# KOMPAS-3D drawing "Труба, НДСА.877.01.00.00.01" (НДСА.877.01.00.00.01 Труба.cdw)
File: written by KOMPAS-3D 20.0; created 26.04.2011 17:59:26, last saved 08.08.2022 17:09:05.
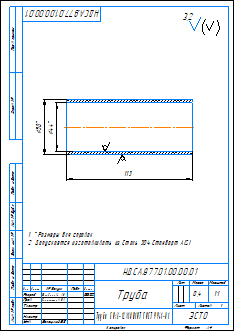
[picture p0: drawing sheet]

Sheet 1: A4, portrait

Document properties: Автор: Мочегов И.Н.; Организация: ЭСТО-Вакуум; Масса: 0.395434; Знак неуказанной шероховатости: 4; Параметр неуказанной шероховатости: 3,2; 311081399727: <item xmlns="http://appius.ru/pdm" xmlns:xs="http://www.w3.org/2001/XMLSchema" xmlns:xsi="http://www.w3.org/2001/XMLSchema-instance" xsi:type="item">  <element xmlns:d2p1="http://v8.1c.ru/8.1/data/enterprise/current-config" xsi:type="d2p1:CatalogRef.aps_Элемен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; 311081399827: <item xmlns="http://appius.ru/pdm" xmlns:xs="http://www.w3.org/2001/XMLSchema" xmlns:xsi="http://www.w3.org/2001/XMLSchema-instance" xsi:type="item">  <element xmlns:d2p1="http://v8.1c.ru/8.1/data/enterprise/current-config" xsi:type="d2p1:CatalogRef.aps_Элемен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; 255363910193: <item xmlns="http://appius.ru/pdm" xmlns:xs="http://www.w3.org/2001/XMLSchema" xmlns:xsi="http://www.w3.org/2001/XMLSchema-instance" xsi:type="item">  <element xmlns:d2p1="http://v8.1c.ru/8.1/data/enterprise/current-config" xsi:type="d2p1:CatalogRef.aps_Элемен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; 255363910293: <item xmlns="http://appius.ru/pdm" xmlns:xs="http://www.w3.org/2001/XMLSchema" xmlns:xsi="http://www.w3.org/2001/XMLSchema-instance" xsi:type="item">  <element xmlns:d2p1="http://v8.1c.ru/8.1/data/enterprise/current-config" xsi:type="d2p1:CatalogRef.aps_Элемен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; PDM_DOCXDTO: <item xmlns="http://appius.ru/pdm" xmlns:xs="http://www.w3.org/2001/XMLSchema" xmlns:xsi="http://www.w3.org/2001/XMLSchema-instance" xsi:type="item">  <element xmlns:d2p1="http://v8.1c.ru/8.1/data/enterprise/current-config" xsi:type="d2p1:CatalogRef.aps_Элемен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; PDM_ITEMXDTO: <item xmlns="http://appius.ru/pdm" xmlns:xs="http://www.w3.org/2001/XMLSchema" xmlns:xsi="http://www.w3.org/2001/XMLSchema-instance" xsi:type="item">  <element xmlns:d2p1="http://v8.1c.ru/8.1/data/enterprise/current-config" xsi:type="d2p1:CatalogRef.aps_Элемен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; PLM_CDWXDTO: <item xmlns="http://appius.ru/pdm" xmlns:xs="http://www.w3.org/2001/XMLSchema" xmlns:xsi="http://www.w3.org/2001/XMLSchema-instance" xsi:type="item">  <element xmlns:d2p1="http://v8.1c.ru/8.1/data/enterprise/current-config" xsi:type="d2p1:CatalogRef.aps_Элемен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; Полное имя файла: ..\..\PLM\НДСА.877.01.00.00.01 Труба.m3d; PDM_DOCXDTO: <item xmlns="http://appius.ru/pdm" xmlns:xs="http://www.w3.org/2001/XMLSchema" xmlns:xsi="http://www.w3.org/2001/XMLSchema-instance" xsi:type="item">  <element xmlns:d2p1="http://v8.1c.ru/8.1/data/enterprise/current-config" xsi:type="d2p1:CatalogRef.aps_Элемен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; PDM_ITEMXDTO: <item xmlns="http://appius.ru/pdm" xmlns:xs="http://www.w3.org/2001/XMLSchema" xmlns:xsi="http://www.w3.org/2001/XMLSchema-instance" xsi:type="item">  <element xmlns:d2p1="http://v8.1c.ru/8.1/data/enterprise/current-config" xsi:type="d2p1:CatalogRef.aps_Элемен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

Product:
- Part/product: Труба  | designation НДСА.877.01.00.00.01
    Материал: Труба  50х3-12Х18Н10Т ГОСТ 9941-81 (density 7900 kg/m3)
    Масса: 0.395434
    Раздел спецификации: Детали
    Форматы листов документа: A4
    additional columns: <item xmlns="http://appius.ru/pdm" xmlns:xs="http://www.w3.org/2001/XMLSchema" x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; <item xmlns="http://appius.ru/pdm" xmlns:xs="http://www.w3.org/2001/XMLSchema" x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; <item xmlns="http://appius.ru/pdm" xmlns:xs="http://www.w3.org/2001/XMLSchema" x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; <item xmlns="http://appius.ru/pdm" xmlns:xs="http://www.w3.org/2001/XMLSchema" x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; <item xmlns="http://appius.ru/pdm" xmlns:xs="http://www.w3.org/2001/XMLSchema" x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; <item xmlns="http://appius.ru/pdm" xmlns:xs="http://www.w3.org/2001/XMLSchema" x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

Title block, sheet 1: Наименование: Труба; designation: НДСА.877.01.00.00.01; Материал: Труба  50х3-12Х18Н10Т ГОСТ 9941-81; Масса: 0,4; scale: 1:1; Количество листов документа: 1; organisation: ЭСТО; Форматы листов документа: A4; stored path: C:\_Мочегов\Приказ №2-11 Разработка нагревателей\Накальный (Гор) УКРД.772.05-01\_В PDM\УКРД.772.08.02.00.01 Труба.cdw; Разработал: Щербакова А.В.; Проверил: Горностаев П.А.; Утвердил: Белецкий В.Е.; Разработал, date: 08.08.2022

Views: Вид 1, Местный разрез 1, Спереди
Referenced files in C:\Users\cherbakova\Desktop\PLM\: НДСА.876.01.00.00.02 Труба.m3d, НДСА.877.01.00.00.01 Труба.m3d
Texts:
  Линейный размер
  НДСА.877.01.00.00.01 Труба
Dimensions and other numbers on the sheet: 44; 50; 113; 3,2; 1:1; 1; 0,4; 08.08.2022; 2

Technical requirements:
  *Размеры для справок
  Допускается изготавливать из Сталь 304 Стандарт AISI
